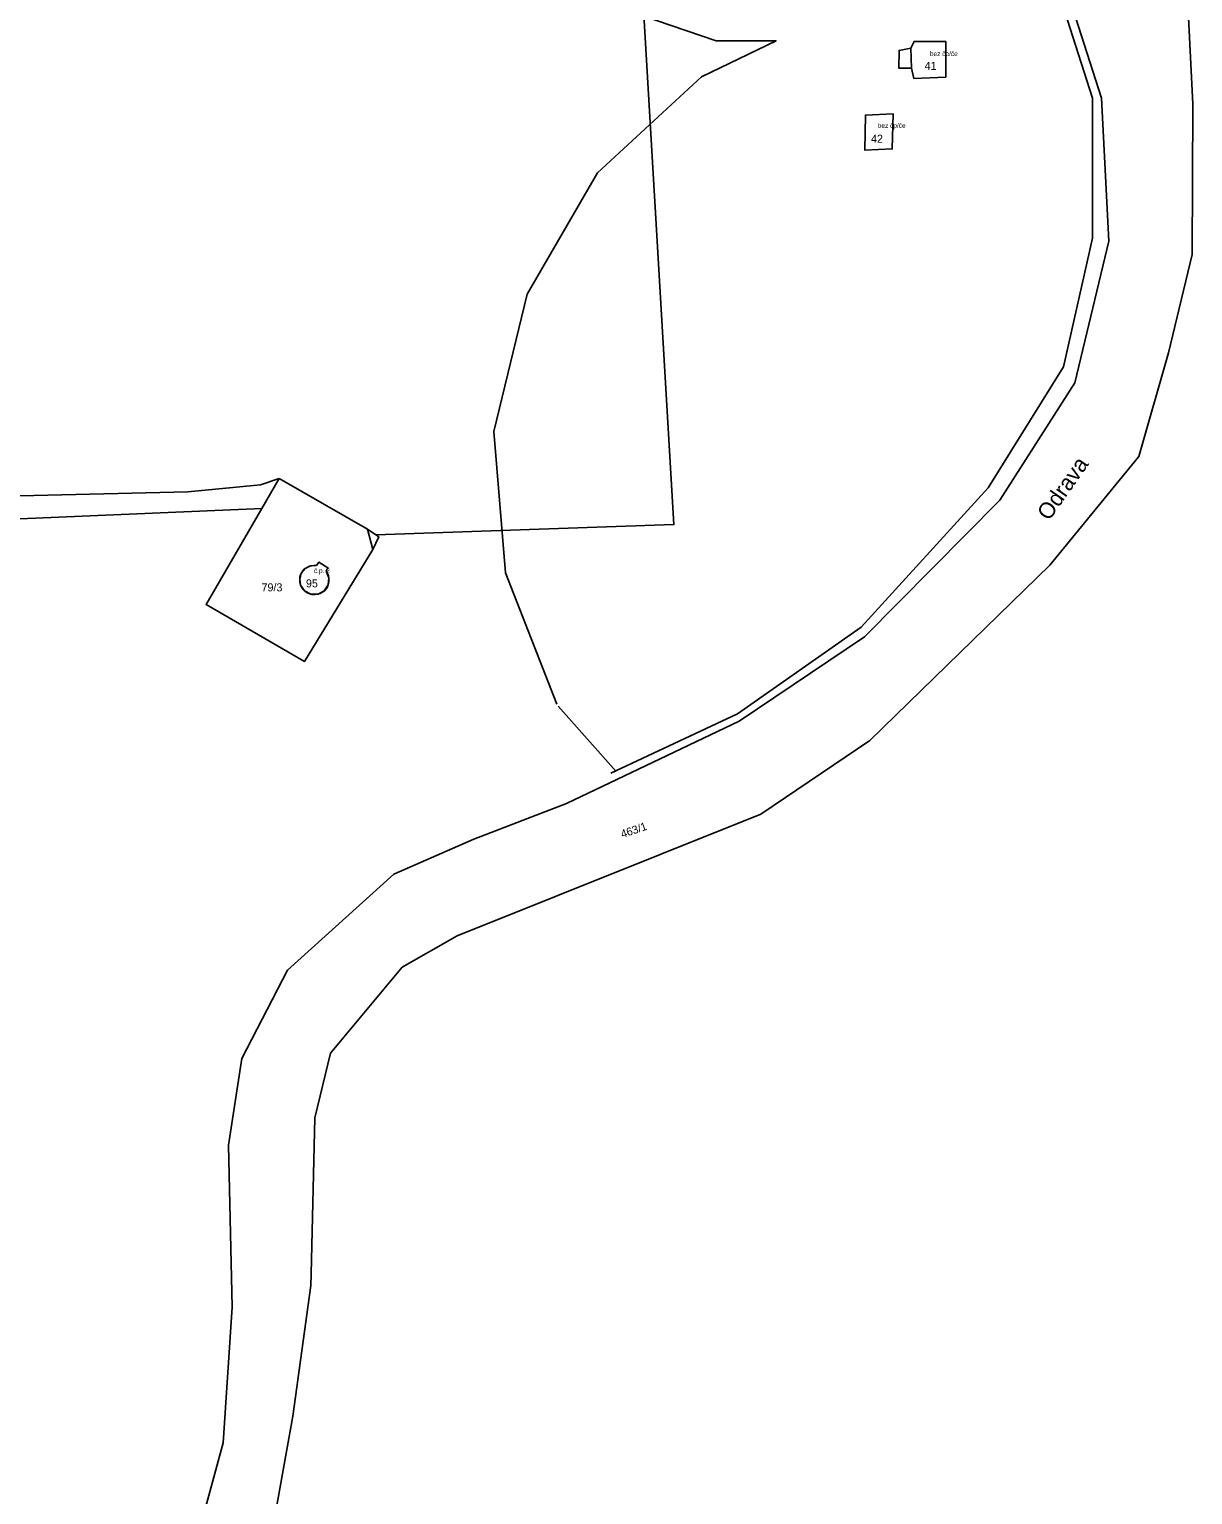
# Model space of a CAD drawing. Extents: x -882150 to -879379, y -1022570 to -1019819.
# Drawn here: x -879708.9 to -879461.8, y -1020448.8 to -1020137.6 of the extents above; entities that cross this region are included whole.
import ezdxf

# ---------------------------------------------------------------- set-up
doc = ezdxf.new("R2010")
doc.units = 0
for name, color, linetype in [('Definiční body', 7, 'Continuous'), ('Hranice parcel', 7, 'Continuous'), ('Parcelní čísla', 7, 'Continuous'), ('Polygon budovy', 7, 'Continuous'), ('Pop  PČ popisy', 7, 'Continuous'), ('Vnitřní kresba', 7, 'Continuous')]:
    doc.layers.add(name, color=color, linetype=linetype)

msp = doc.modelspace()

# ---------------------------------------------------------------- linework, layer by layer
at = {"layer": 'Hranice parcel'}
for p, q in [((-879461.84, -1020153.53), (-879462.72, -1020135.04)), ((-879659.57, -1020239.36), (-879655.86, -1020233)), ((-879649.15, -1020404.38), (-879649.09, -1020401.92))]:
    msp.add_line(p, q, dxfattribs=at)
for points in [[(-879588.59, -1019960.72), (-879588.56, -1019961.2), (-879580.3, -1020101.99), (-879572.03, -1020242.79), (-879635.31, -1020244.96)], [(-879677.18, -1020472.46), (-879667.75, -1020437.8), (-879665.81, -1020409.01), (-879666.61, -1020374.63), (-879663.82, -1020356.18), (-879654.07, -1020337.43), (-879631.48, -1020317.07), (-879614.53, -1020309.6), (-879594.85, -1020302.07), (-879558.14, -1020284.55), (-879531.56, -1020266.67), (-879502.78, -1020237.58), (-879486.9, -1020212.69), (-879479.67, -1020182.61), (-879481.19, -1020152.24), (-879491.62, -1020119.75), (-879498.99, -1020091.88), (-879503.51, -1020033.88), (-879504.65, -1020019.83), (-879508.77, -1019990.39), (-879509.31, -1019962.82)], [(-879521.67, -1020141.64), (-879524.19, -1020142.11), (-879524.23, -1020145.89), (-879521.55, -1020145.84), (-879521.04, -1020148.06), (-879514.28, -1020147.77), (-879514.28, -1020140.23), (-879521, -1020140.18), (-879521.67, -1020141.64)], [(-879473.25, -1020228.32), (-879466.97, -1020206.3), (-879461.95, -1020185.45), (-879461.84, -1020153.53)], [(-879525.47, -1020155.58), (-879531.36, -1020155.84), (-879531.47, -1020163.28), (-879525.65, -1020163), (-879525.47, -1020155.58)], [(-879655.86, -1020233), (-879659.82, -1020234.34), (-879675.23, -1020235.81), (-879713.88, -1020236.74), (-879806.39, -1020228.37), (-879903.87, -1020220.02), (-879966.1, -1020214.66), (-879999.98, -1020211.85)], [(-879659.57, -1020239.36), (-879714.23, -1020241.72), (-879727.52, -1020242.58), (-879810.24, -1020235.23), (-879903.34, -1020226.38), (-879943.69, -1020222.8), (-879966.51, -1020220.46), (-880019.11, -1020215.44), (-880019.8, -1020217.31)], [(-879530.39, -1020288.64), (-879492.21, -1020251.42), (-879473.25, -1020228.32)], [(-879635.31, -1020244.96), (-879637.07, -1020243.78), (-879655.86, -1020233)], [(-879635.31, -1020244.96), (-879634.69, -1020245.37), (-879635.93, -1020248.09), (-879650.48, -1020271.88), (-879671.38, -1020259.75), (-879659.57, -1020239.36)], [(-879647.95, -1020251.5), (-879647.45, -1020250.79), (-879645.5, -1020251.98), (-879645.89, -1020252.69)], [(-879645.89, -1020252.69), (-879645.596, -1020253.164), (-879645.391, -1020253.683), (-879645.283, -1020254.231), (-879645.274, -1020254.789), (-879645.364, -1020255.339), (-879645.551, -1020255.865), (-879645.83, -1020256.349), (-879646.19, -1020256.775), (-879646.62, -1020257.13), (-879646.679, -1020257.17), (-879647.172, -1020257.431), (-879647.704, -1020257.601), (-879648.257, -1020257.672), (-879648.814, -1020257.644), (-879649.358, -1020257.517), (-879649.87, -1020257.295), (-879650.334, -1020256.985), (-879650.735, -1020256.597), (-879651.06, -1020256.144), (-879651.3, -1020255.64), (-879651.448, -1020255.104), (-879651.497, -1020254.551), (-879651.447, -1020253.998), (-879651.298, -1020253.462), (-879651.055, -1020252.962), (-879650.888, -1020252.713), (-879650.518, -1020252.298), (-879650.08, -1020251.957), (-879649.587, -1020251.7), (-879649.056, -1020251.535), (-879648.505, -1020251.468), (-879647.95, -1020251.5)], [(-879649.09, -1020401.92), (-879648.26, -1020368.81), (-879644.96, -1020355.05), (-879629.7, -1020336.78), (-879618.03, -1020330.13), (-879553.57, -1020304.27), (-879530.39, -1020288.64)], [(-879658.32, -1020462.18), (-879652.92, -1020432.12), (-879649.15, -1020404.38)]]:
    msp.add_lwpolyline(points, dxfattribs=at)
at = {"layer": 'Polygon budovy'}
for points in [[(-879521.67, -1020141.64), (-879521.55, -1020145.84), (-879521.04, -1020148.06), (-879514.28, -1020147.77), (-879514.28, -1020140.23), (-879521, -1020140.18)], [(-879525.65, -1020163), (-879525.47, -1020155.58), (-879531.36, -1020155.84), (-879531.47, -1020163.28)], [(-879645.89, -1020252.69), (-879645.5, -1020251.98), (-879647.45, -1020250.79), (-879647.95, -1020251.5), (-879649.223, -1020251.575), (-879650.357, -1020252.157), (-879651.159, -1020253.149), (-879651.493, -1020254.379), (-879651.3, -1020255.64), (-879650.448, -1020256.889), (-879649.108, -1020257.589), (-879647.596, -1020257.575), (-879646.269, -1020256.852), (-879645.439, -1020255.588), (-879645.302, -1020254.083)]]:
    msp.add_lwpolyline(points, close=True, dxfattribs=at)
at = {"layer": 'Vnitřní kresba'}
for p, q in [((-879521.67, -1020141.64), (-879521.55, -1020145.84)), ((-879637.07, -1020243.78), (-879635.93, -1020248.09)), ((-879532.28, -1020264.56), (-879558.53, -1020282.97)), ((-879596.61, -1020281.36), (-879584.26, -1020295.26)), ((-879558.53, -1020282.97), (-879585.42, -1020295.58))]:
    msp.add_line(p, q, dxfattribs=at)
for points in [[(-879548.1, -1019959.3), (-879577.68, -1019963.91), (-879604.17, -1019978.16), (-879624.6, -1020000.35), (-879636.57, -1020027.66), (-879639.14, -1020057.51), (-879631.73, -1020086.8), (-879615.2, -1020111.72), (-879591.51, -1020130.32), (-879563.07, -1020140.04), (-879550.31, -1020140.04), (-879566.18, -1020147.67), (-879588.25, -1020168.06), (-879603.19, -1020193.89), (-879610.24, -1020223.02), (-879607.79, -1020253.06), (-879596.91, -1020280.95)], [(-879518.25, -1019963.85), (-879510.79, -1019968.87), (-879510.53, -1019990.75), (-879505.64, -1020020.23), (-879504.74, -1020034.13), (-879500.88, -1020090.97), (-879493.16, -1020120.83), (-879489.04, -1020133.7), (-879483.12, -1020152.24), (-879483.12, -1020181.98), (-879489.3, -1020209.27), (-879505.25, -1020235.02), (-879532.28, -1020264.56)]]:
    msp.add_lwpolyline(points, dxfattribs=at)

# ---------------------------------------------------------------- texts
at = {"layer": 'Definiční body'}
for s, p in [('bez čp/če', (-879517.64, -1020143.3)), ('bez čp/če', (-879528.72, -1020158.54)), ('č.p. 2', (-879648.47, -1020253.1))]:
    msp.add_text(s, height=1, dxfattribs=at).set_placement(p)
at = {"layer": 'Parcelní čísla'}
for s, p in [('41', (-879518.77, -1020146.22)), ('42', (-879530.16, -1020161.7)), ('79/3', (-879659.6, -1020256.98)), ('95', (-879650.167, -1020256.13))]:
    msp.add_text(s, height=1.7, dxfattribs=at).set_placement(p)
msp.add_text('463/1', height=1.7, rotation=19, dxfattribs=at).set_placement((-879582.973, -1020309.413))
at = {"layer": 'Pop  PČ popisy'}
msp.add_text('Odrava', height=3.4, rotation=55, dxfattribs=at).set_placement((-879492.357, -1020242.155))

doc.saveas('drawing.dxf')
